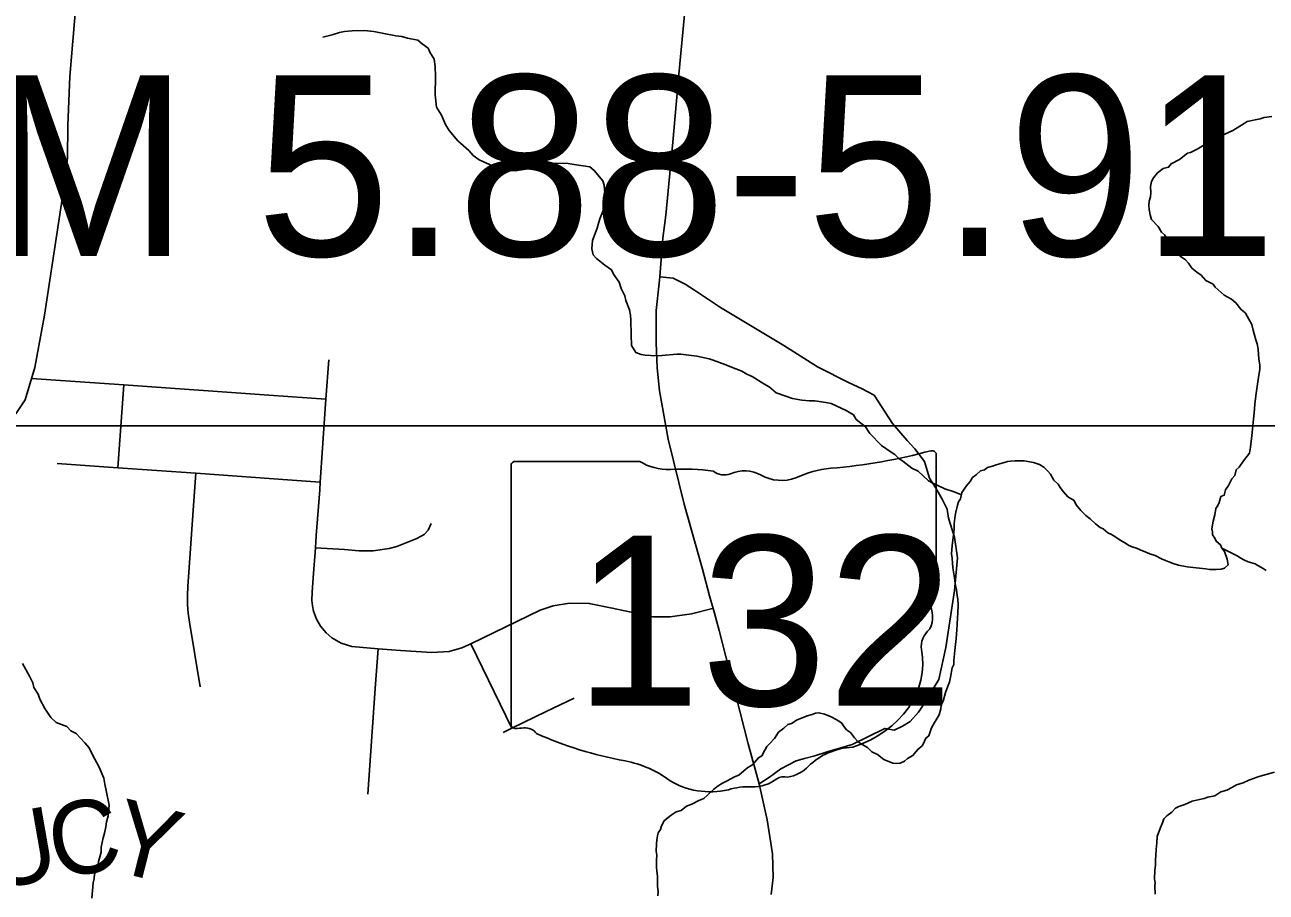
# Model space of a CAD drawing. Extents: x 0 to 39.3, y -3.9 to 22.
# Drawn here: x 5.137 to 6.099, y 19.208 to 19.881 of the extents above; entities that cross this region are included whole.
import ezdxf

# ---------------------------------------------------------------- set-up
doc = ezdxf.new("R2010")
doc.units = 0
for name, color, linetype in [('GM_X_Minor_River', 7, 'Continuous'), ('GM_X_State_Location', 7, 'Continuous'), ('GM_X_State_Route', 7, 'Continuous'), ('GM_X_State_Shield', 7, 'Continuous'), ('GM_X_Township_Road', 7, 'Continuous'), ('GM_X_Township_Road_Text', 7, 'Continuous'), ('SH_Text', 7, 'Continuous')]:
    doc.layers.add(name, color=color, linetype=linetype)

msp = doc.modelspace()

# ---------------------------------------------------------------- linework, layer by layer
at = {"layer": 'GM_X_Minor_River'}
for points in [[(5.40746, 19.87553), (5.39987, 19.87643), (5.39074, 19.87621), (5.38465, 19.87555), (5.38083, 19.87486), (5.3751, 19.87306), (5.37091, 19.87199), (5.36785, 19.87129)], [(5.8629, 19.51622), (5.85993, 19.51774), (5.85653, 19.51894), (5.85011, 19.52096), (5.84407, 19.52372), (5.84067, 19.5253), (5.83729, 19.52726), (5.82942, 19.53463), (5.82452, 19.537), (5.81739, 19.54244), (5.81438, 19.5444), (5.81139, 19.54749), (5.80838, 19.54945), (5.80087, 19.55452), (5.7919, 19.56381), (5.78857, 19.56919), (5.78144, 19.57464), (5.77922, 19.57848), (5.77357, 19.58162), (5.76188, 19.58715), (5.75771, 19.58799), (5.74937, 19.58927), (5.74519, 19.58935), (5.73911, 19.58983), (5.73191, 19.5911), (5.71944, 19.5955), (5.71381, 19.60017), (5.70967, 19.60252), (5.70064, 19.608), (5.69649, 19.60998), (5.69273, 19.61233), (5.68328, 19.61591), (5.68026, 19.61711), (5.67044, 19.6207), (5.66742, 19.6219), (5.65795, 19.62397), (5.64543, 19.62533), (5.64239, 19.62538), (5.63058, 19.62445), (5.6264, 19.62414), (5.61766, 19.62467), (5.61463, 19.62511), (5.61047, 19.6267), (5.60714, 19.63208), (5.6069, 19.64045), (5.60671, 19.65186), (5.6064, 19.65567), (5.60571, 19.65987), (5.60279, 19.66714), (5.60208, 19.67058), (5.59914, 19.67633), (5.5977, 19.6813), (5.59325, 19.68747), (5.59178, 19.69091), (5.58652, 19.69443), (5.58014, 19.69948), (5.57753, 19.70257), (5.57647, 19.70715), (5.57696, 19.71361), (5.58054, 19.72305), (5.58135, 19.72608), (5.58256, 19.73024), (5.58573, 19.73817), (5.58617, 19.74159), (5.58664, 19.7469), (5.58604, 19.75642), (5.58496, 19.75986), (5.57825, 19.76796), (5.57487, 19.77068), (5.56274, 19.77242), (5.55819, 19.77326), (5.54831, 19.77343), (5.54298, 19.77276), (5.5342, 19.77102), (5.53038, 19.76957), (5.52351, 19.76854), (5.51704, 19.76752), (5.50451, 19.7685), (5.49999, 19.77124), (5.48905, 19.776), (5.48454, 19.7795), (5.48119, 19.78336), (5.47257, 19.79074), (5.46586, 19.79884), (5.4629, 19.80345), (5.45998, 19.81073), (5.4559, 19.81688), (5.45492, 19.82641), (5.45516, 19.84085), (5.45491, 19.84846), (5.45424, 19.85418), (5.45091, 19.85956), (5.44944, 19.86263), (5.44494, 19.86613), (5.44156, 19.86885), (5.43361, 19.87051), (5.42907, 19.87173), (5.42451, 19.87219), (5.4139, 19.87428), (5.40746, 19.87553)], [(6.10359, 19.80968), (6.0975, 19.80902), (6.09444, 19.80794), (6.08452, 19.80583), (6.08221, 19.80435), (6.07337, 19.7988), (6.06188, 19.79368), (6.05954, 19.7903), (6.05075, 19.78741), (6.04576, 19.78446), (6.04039, 19.78189), (6.0381, 19.78117), (6.03194, 19.77633), (6.02542, 19.77303), (6.02348, 19.7704), (6.01927, 19.76933), (6.01504, 19.76598), (6.01193, 19.76223), (6.01036, 19.75922), (6.00954, 19.75543), (6.00983, 19.75048), (6.0094, 19.74745), (6.00858, 19.74404), (6.00815, 19.74063), (6.00848, 19.73758), (6.00916, 19.73339), (6.01025, 19.72994), (6.01548, 19.72453), (6.01806, 19.71992), (6.02031, 19.71798), (6.02179, 19.71567), (6.0244, 19.71258), (6.02661, 19.70836), (6.03149, 19.70447), (6.03258, 19.70141), (6.03671, 19.69868), (6.03895, 19.69598), (6.04155, 19.69213), (6.0453, 19.68902), (6.04868, 19.68668), (6.05241, 19.68243), (6.05806, 19.67967), (6.05955, 19.67736), (6.06667, 19.67115), (6.07232, 19.66801), (6.07569, 19.66529), (6.07941, 19.66029), (6.08316, 19.65718), (6.08574, 19.65257), (6.08795, 19.64835), (6.08902, 19.64415), (6.08973, 19.64109), (6.09118, 19.6365), (6.09226, 19.63344), (6.09295, 19.62925), (6.09358, 19.62163), (6.09427, 19.61705), (6.09421, 19.61363), (6.09337, 19.60908), (6.0925, 19.60225), (6.09121, 19.59315), (6.09034, 19.5867), (6.08984, 19.57987), (6.08938, 19.57493), (6.08849, 19.56734), (6.08803, 19.56241), (6.08712, 19.55329), (6.08628, 19.54875), (6.08162, 19.54275), (6.07811, 19.53786), (6.07579, 19.53562), (6.07496, 19.53145), (6.07264, 19.52883)], [(6.07264, 19.52883), (6.06989, 19.52356), (6.06755, 19.52018), (6.06672, 19.51601), (6.06404, 19.51491), (6.06282, 19.51037), (6.06164, 19.50811), (6.06008, 19.50586), (6.05924, 19.50093), (6.05802, 19.496), (6.05716, 19.48993), (6.0575, 19.48765), (6.05746, 19.48537), (6.05932, 19.48267), (6.06042, 19.48037), (6.06379, 19.47765), (6.06489, 19.47497), (6.06674, 19.47227), (6.06893, 19.46653), (6.06961, 19.46196), (6.06691, 19.45934), (6.06423, 19.45863), (6.06043, 19.45832), (6.05511, 19.45841), (6.05245, 19.45884), (6.04486, 19.45973), (6.03804, 19.46061), (6.03121, 19.46187), (6.02705, 19.46308), (6.02365, 19.46428), (6.02101, 19.46547), (6.01799, 19.46667), (6.01309, 19.46941), (6.00893, 19.47063), (6.00591, 19.47182), (6.00138, 19.4738), (5.99874, 19.47499), (5.99609, 19.4758), (5.99269, 19.477), (5.99006, 19.47895), (5.98592, 19.4813), (5.98178, 19.48404), (5.97915, 19.4856), (5.97651, 19.48679), (5.97276, 19.4899), (5.9705, 19.49108), (5.96674, 19.49381), (5.96262, 19.49768), (5.95925, 19.5004), (5.95551, 19.50427), (5.95178, 19.50852), (5.95032, 19.51197), (5.94542, 19.51472), (5.94207, 19.51858), (5.93946, 19.52204), (5.93799, 19.52473), (5.93462, 19.52783), (5.93204, 19.53244), (5.92979, 19.53476), (5.9268, 19.53786), (5.92341, 19.53982), (5.91888, 19.54142), (5.91168, 19.54269), (5.90446, 19.54282), (5.90103, 19.5425), (5.89874, 19.54215), (5.8953, 19.54108), (5.88996, 19.53965), (5.8869, 19.53856), (5.88308, 19.53749), (5.88076, 19.53563), (5.87771, 19.53492), (5.87424, 19.53194), (5.87154, 19.5297), (5.86959, 19.5267), (5.86648, 19.52295), (5.86493, 19.52069), (5.86336, 19.51806), (5.86214, 19.51314), (5.86058, 19.51088), (5.85977, 19.50824), (5.85855, 19.50293), (5.85812, 19.50028), (5.85726, 19.49421), (5.85718, 19.48965), (5.85673, 19.48509), (5.85628, 19.4813), (5.85583, 19.47712), (5.85534, 19.47067), (5.85566, 19.46724), (5.8563, 19.45962), (5.85733, 19.45352), (5.85835, 19.4459), (5.85905, 19.44284), (5.85939, 19.44017), (5.86007, 19.43522), (5.86038, 19.43141), (5.86026, 19.42418), (5.85983, 19.42115), (5.85974, 19.41583), (5.85929, 19.41165)], [(6.06489, 19.47497), (6.07657, 19.46906), (6.07958, 19.46711), (6.08184, 19.46593), (6.08524, 19.46434), (6.09053, 19.46273), (6.0928, 19.46155), (6.09694, 19.45919), (6.09919, 19.45763)], [(5.85929, 19.41165), (5.8588, 19.40482), (5.85788, 19.39571), (5.85746, 19.39305), (5.85741, 19.39039), (5.85699, 19.38774), (5.85694, 19.38469), (5.85575, 19.38205), (5.85449, 19.37485), (5.85367, 19.37106), (5.85248, 19.36804), (5.85049, 19.36313), (5.84886, 19.35631), (5.84728, 19.3533), (5.84685, 19.35026), (5.84564, 19.34572), (5.84173, 19.33933), (5.83976, 19.33556), (5.83776, 19.32951), (5.83545, 19.32765), (5.83427, 19.32539), (5.83269, 19.32199), (5.82883, 19.31864), (5.82534, 19.31413), (5.82112, 19.31193), (5.8188, 19.30969), (5.81535, 19.30823), (5.81269, 19.30789), (5.80965, 19.30833), (5.80286, 19.31111), (5.79798, 19.315), (5.79345, 19.31698), (5.79009, 19.32046), (5.78783, 19.32164), (5.78482, 19.32359), (5.78256, 19.32515), (5.77995, 19.32786), (5.77698, 19.3321), (5.77397, 19.33405), (5.77211, 19.33637), (5.76988, 19.33945), (5.76574, 19.34218), (5.76197, 19.34415), (5.75895, 19.34535), (5.75668, 19.34615), (5.75252, 19.34736), (5.74986, 19.34703), (5.74718, 19.34593), (5.74336, 19.34486), (5.7403, 19.34377), (5.7357, 19.34195), (5.73109, 19.33899), (5.72842, 19.33828), (5.72533, 19.33529), (5.72109, 19.33232), (5.71797, 19.32743), (5.7141, 19.32332), (5.71216, 19.32107), (5.7106, 19.31843), (5.70824, 19.31391), (5.70555, 19.31244), (5.7009, 19.30682), (5.69744, 19.30497), (5.69436, 19.30237), (5.6905, 19.29901), (5.68705, 19.29755), (5.68476, 19.29645), (5.68092, 19.29424), (5.67785, 19.29277), (5.67439, 19.29055), (5.67093, 19.28795), (5.6659, 19.28309), (5.6632, 19.28086), (5.65938, 19.27941), (5.65401, 19.27646), (5.6498, 19.27501), (5.64556, 19.27166), (5.64174, 19.27059), (5.6379, 19.268), (5.63558, 19.26613), (5.6325, 19.26353), (5.63054, 19.25976), (5.62972, 19.25673), (5.62778, 19.2541), (5.62736, 19.25183), (5.62693, 19.24879), (5.62649, 19.24538), (5.6264, 19.24005), (5.62673, 19.237), (5.62667, 19.2332), (5.62657, 19.2275), (5.6269, 19.22445), (5.62722, 19.22064), (5.62746, 19.21265), (5.62778, 19.20884), (5.62772, 19.20542)], [(5.15229, 19.3507), (5.14861, 19.35799), (5.14716, 19.36182), (5.14382, 19.36683), (5.14312, 19.37064), (5.14054, 19.37563), (5.13501, 19.38562)], [(5.18897, 19.20364), (5.18993, 19.21541), (5.19075, 19.21882), (5.19081, 19.22224), (5.19356, 19.2279), (5.19401, 19.23208), (5.19603, 19.23926), (5.1961, 19.24307), (5.19774, 19.25026), (5.19856, 19.25405), (5.19979, 19.25897), (5.20023, 19.26277), (5.20145, 19.26731), (5.20235, 19.27566), (5.19988, 19.28711), (5.19883, 19.29208), (5.19814, 19.29665), (5.19448, 19.30509), (5.18932, 19.31468), (5.18675, 19.32005), (5.18339, 19.32391), (5.17667, 19.33126), (5.17252, 19.33323), (5.16954, 19.33671), (5.16123, 19.3399), (5.15711, 19.34377), (5.15229, 19.3507)], [(6.10569, 19.30122), (6.0927, 19.29765), (6.09002, 19.29655), (6.08581, 19.29511), (6.08122, 19.2929), (6.07625, 19.29147), (6.07318, 19.28962), (6.06858, 19.28742), (6.06399, 19.28598), (6.05938, 19.28302), (6.05404, 19.28197), (6.05098, 19.28088), (6.04755, 19.28018), (6.04182, 19.27876), (6.03608, 19.2762), (6.03149, 19.27476), (6.0288, 19.27329), (6.02609, 19.27029), (6.02224, 19.26732), (6.01992, 19.26508), (6.01873, 19.26206), (6.01714, 19.25828), (6.01475, 19.25148), (6.01429, 19.24654), (6.01382, 19.24122), (6.01374, 19.23666), (6.0133, 19.23325), (6.01324, 19.22945), (6.01278, 19.22489), (6.01267, 19.21843), (6.013, 19.21538), (6.01296, 19.2131), (6.01323, 19.20663)]]:
    msp.add_lwpolyline(points, dxfattribs=at)
at = {"layer": 'GM_X_State_Route'}
for points in [[(5.63269, 19.72524), (5.63368, 19.73315), (5.63928, 19.78995), (5.64385, 19.84237), (5.65234, 19.9327), (5.65834, 19.99886), (5.66296, 20.04649), (5.66741, 20.08755), (5.67364, 20.17213), (5.68132, 20.27141), (5.68608, 20.34046), (5.69072, 20.41095), (5.69558, 20.47319), (5.6968, 20.49078), (5.6985, 20.50343), (5.70197, 20.51982)], [(5.71549, 19.2064), (5.71709, 19.21966), (5.71647, 19.23781), (5.71247, 19.26431), (5.7062, 19.29232), (5.69753, 19.32326), (5.68795, 19.36068), (5.67508, 19.41108), (5.67142, 19.42448), (5.66776, 19.43789), (5.66217, 19.45863), (5.64803, 19.50908), (5.63559, 19.5595), (5.62881, 19.59687), (5.62717, 19.61477), (5.62633, 19.63419), (5.62631, 19.65929), (5.62853, 19.68056), (5.62908, 19.68527), (5.63145, 19.71534), (5.63269, 19.72524)]]:
    msp.add_lwpolyline(points, dxfattribs=at)
at = {"layer": 'GM_X_State_Shield'}
for p, q in [((5.84342, 19.44253), (5.84342, 19.54722)), ((5.51383, 19.53881), (5.51383, 19.33869)), ((5.6136, 19.54226), (5.51708, 19.54226)), ((5.84339, 19.44256), (5.84342, 19.44253))]:
    msp.add_line(p, q, dxfattribs=at)
for centre, major_axis, start_param, end_param in [((5.72601, 19.81509), (0.34952, 0), 4.814394, 5.042369), ((5.83976, 19.54765), (0.00367, 0), 6.141152, 7.989035), ((5.51761, 19.53924), (0.00382, 0), 1.712693, 3.28349), ((5.63659, 19.56549), (0.03703, 0), 4.042523, 4.731795), ((5.64886, 19.42991), (0.13295, 0), 1.404758, 1.657858), ((5.67905, 19.54028), (0.01068, 0), 3.836095, 5.185415), ((5.69473, 19.51715), (0.02221, 0), 0.950623, 2.079405), ((5.7706, 19.48113), (0.07032, 0), 1.699011, 2.107814), ((5.7234, 19.54887), (0.02672, 0), 4.081561, 5.145723), ((5.84257, 19.43485), (0.00568, 0), 1.883978, 3.671073), ((5.8395, 19.44213), (0.00393, 0), 5.05454, 6.418171), ((5.80645, 19.42161), (0.03409, 0), 5.934695, 6.695948), ((5.85656, 19.39872), (0.0248, 0), 2.387724, 3.262537), ((5.74559, 19.3854), (0.08742, 0), 5.101752, 6.440018), ((5.51764, 19.33825), (0.00385, 0), 3.00124, 4.508301), ((5.51823, 19.35873), (0.0294, 0), 4.665946, 4.897461), ((5.52424, 19.32715), (0.0106, 0), 0.519207, 1.627899), ((5.65807, 19.50695), (0.2524, 0), 4.195997, 4.488961), ((5.78246, 19.28251), (0.04788, 0), 1.647645, 2.488434), ((5.58282, 19.24879), (0.07897, 0), 0.823519, 1.323587), ((5.72179, 19.3193), (0.02824, 0), 4.937069, 5.64225), ((5.66823, 19.32615), (0.05011, 0), 4.026481, 4.996735), ((5.70085, 19.31117), (0.0267, 0), 4.691044, 5.507374), ((5.725, 19.29179), (0.00752, 0), 1.147584, 2.315152), ((5.69718, 19.25696), (0.04118, 0), 1.495662, 1.94098)]:
    msp.add_ellipse(centre, major_axis=major_axis, ratio=0.8, start_param=start_param, end_param=end_param, dxfattribs=at)
at = {"layer": 'GM_X_Township_Road'}
for p, q in [((5.3725, 19.62106), (5.37034, 19.5905)), ((5.20901, 19.5373), (5.21354, 19.60163)), ((5.32607, 19.59362), (5.37034, 19.5905)), ((5.37034, 19.5905), (5.36582, 19.52627)), ((5.26823, 19.51542), (5.26947, 19.53305)), ((5.3441, 19.52779), (5.36582, 19.52627)), ((5.51447, 19.33526), (5.48257, 19.40083)), ((5.40853, 19.36622), (5.4109, 19.39699)), ((5.40291, 19.28429), (5.40853, 19.36622))]:
    msp.add_line(p, q, dxfattribs=at)
for points in [[(5.13006, 19.57908), (5.1371, 19.58992), (5.14459, 19.61499), (5.15208, 19.65556), (5.16722, 19.7541), (5.17001, 19.77778), (5.17036, 19.80286), (5.17175, 19.84081), (5.18237, 19.96582)], [(5.65599, 19.67493), (5.64869, 19.67972), (5.63945, 19.68448), (5.62908, 19.68527)], [(5.75894, 19.3169), (5.77811, 19.32275), (5.80364, 19.33516), (5.81082, 19.33375), (5.81735, 19.337), (5.82313, 19.34064), (5.82975, 19.34768), (5.83331, 19.35328), (5.84536, 19.37312), (5.85089, 19.39786), (5.85762, 19.44207), (5.85978, 19.46753), (5.85762, 19.48363), (5.85294, 19.49816), (5.85179, 19.5052), (5.84806, 19.51296), (5.84274, 19.522), (5.83814, 19.52919), (5.83427, 19.54211), (5.8268, 19.55203), (5.82076, 19.55849), (5.80956, 19.57156), (5.7952, 19.59353), (5.78543, 19.5987), (5.77595, 19.6033), (5.75125, 19.61566), (5.72539, 19.63203), (5.67627, 19.66162), (5.65599, 19.67493)], [(5.14209, 19.60663), (5.21354, 19.60163), (5.32607, 19.59362)], [(5.16208, 19.54061), (5.20901, 19.5373), (5.26947, 19.53305), (5.3441, 19.52779)], [(5.36582, 19.52627), (5.36548, 19.52011), (5.36281, 19.48473), (5.36212, 19.47526)], [(5.27288, 19.36735), (5.26458, 19.41765), (5.26365, 19.42451), (5.26313, 19.4314), (5.26301, 19.43832), (5.26329, 19.44523), (5.26823, 19.51542)], [(5.36212, 19.47526), (5.38469, 19.47389), (5.39574, 19.47288), (5.40696, 19.4729), (5.41942, 19.47475), (5.42515, 19.47619), (5.44077, 19.48244), (5.44646, 19.48563), (5.44953, 19.48893), (5.45201, 19.49419)], [(5.36212, 19.47526), (5.36043, 19.45194), (5.35962, 19.44087), (5.3594, 19.43445), (5.3598, 19.43022), (5.36068, 19.42607), (5.36295, 19.42001), (5.366, 19.41455), (5.37039, 19.40933), (5.37482, 19.40543), (5.38218, 19.4012), (5.39029, 19.39872), (5.4109, 19.39699)], [(5.48257, 19.40083), (5.53641, 19.42682), (5.54656, 19.43014), (5.559, 19.43222), (5.57444, 19.43206), (5.5922, 19.42853), (5.62388, 19.4216), (5.63726, 19.42177), (5.65381, 19.42396), (5.66995, 19.42814)], [(5.4109, 19.39699), (5.42811, 19.39574), (5.45251, 19.39404), (5.4659, 19.39496), (5.47556, 19.39769), (5.48257, 19.40083)], [(5.50766, 19.33195), (5.51447, 19.33526), (5.54106, 19.3482), (5.56276, 19.35875)], [(5.7062, 19.29232), (5.71424, 19.29743), (5.7229, 19.30392), (5.73481, 19.31011), (5.7413, 19.31197), (5.74935, 19.31397), (5.75894, 19.3169)]]:
    msp.add_lwpolyline(points, dxfattribs=at)
at = {"layer": 'SH_Text'}
msp.add_lwpolyline([(4.86188, 19.96301), (6.19141, 19.96301), (6.19141, 19.56973), (4.86188, 19.56973)], close=True, dxfattribs=at)

# ---------------------------------------------------------------- texts
at = {"layer": 'GM_X_State_Location'}
for s, p in [('s', (5.67492, 19.42545)), ('r', (5.67491, 19.42545))]:
    msp.add_text(s, height=0.000189, dxfattribs=at).set_placement(p)
msp.add_text('132', height=0.000189, rotation=0.00001, dxfattribs=at).set_placement((5.60806, 19.41167))
at = {"layer": 'GM_X_State_Shield'}
msp.add_text('132', height=0.131836, dxfattribs=at).set_placement((5.56283, 19.3528))
at = {"layer": 'GM_X_Township_Road_Text'}
for s, rotation, p in [('U', 9.87735, (5.11109, 19.2099)), ('C', 9.32629, (5.16021, 19.21845)), ('Y', 345.73758, (5.20012, 19.22628))]:
    msp.add_text(s, height=0.05682, rotation=rotation, dxfattribs=at).set_placement(p)
at = {"layer": 'SH_Text'}
msp.add_text('SLM 5.88-5.91', height=0.14, dxfattribs=at).set_placement((4.87915, 19.70165))

doc.saveas('drawing.dxf')
